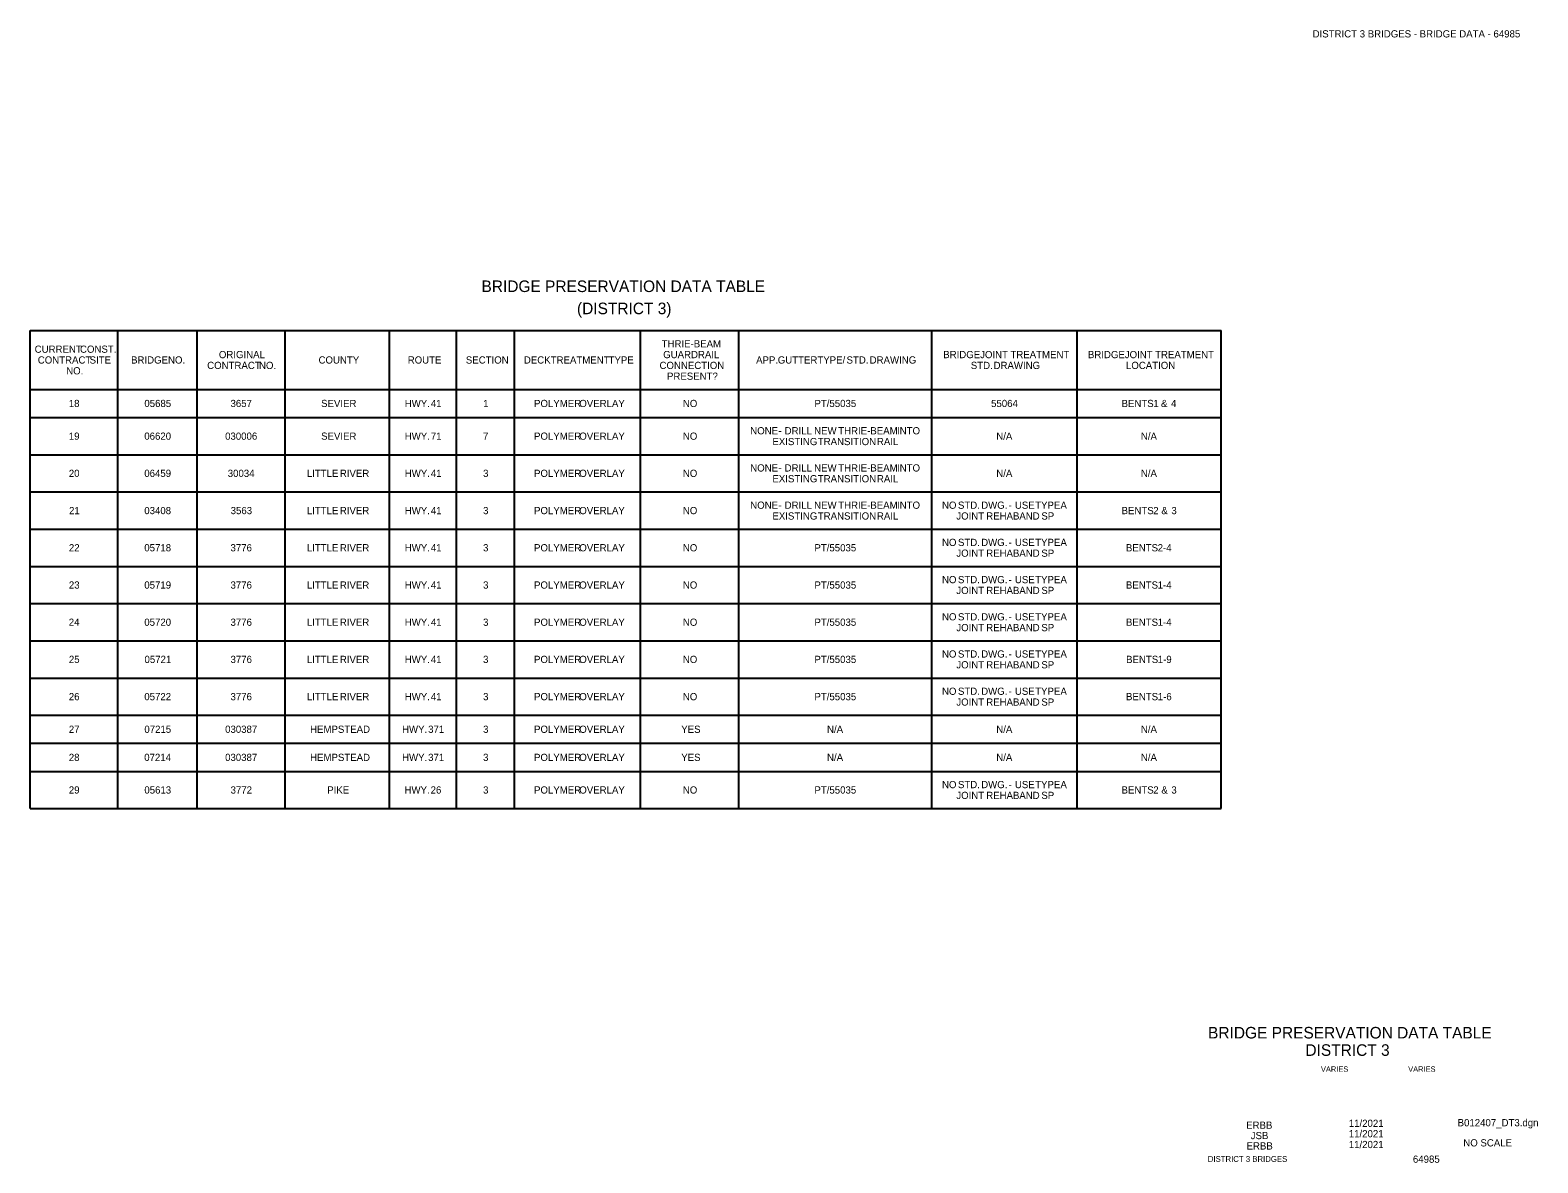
# Model space of a CAD drawing. Extents: x 16 to 1228740, y 11 to 152440.
import ezdxf

# ---------------------------------------------------------------- set-up
doc = ezdxf.new("R2010")
doc.units = 0
for name, color, linetype in [('B_border', 7, 'Continuous'), ('B_Concrete hidden', 7, 'Continuous'), ('Default', 7, 'Continuous')]:
    doc.layers.add(name, color=color, linetype=linetype)

msp = doc.modelspace()

# ---------------------------------------------------------------- linework, layer by layer
at = {"layer": 'B_border'}
msp.add_line((16.2529, 11.9714), (16.2529, 11.9714), dxfattribs=at)
at = {"layer": 'Default'}
for p, q in [((16.2529, 11.9714), (17.9726, 11.9714)), ((16.2529, 11.2809), (16.2529, 11.9714)), ((16.3796, 11.2809), (16.3796, 11.9714)), ((16.4942, 11.2809), (16.4942, 11.9714)), ((16.6209, 11.2809), (16.6209, 11.9714)), ((16.772, 11.2809), (16.772, 11.9714)), ((16.8684, 11.2809), (16.8684, 11.9714)), ((16.9525, 11.2809), (16.9525, 11.9714)), ((17.134, 11.2809), (17.134, 11.9714)), ((17.276, 11.2809), (17.276, 11.9714)), ((17.5548, 11.2809), (17.5548, 11.9714)), ((17.7647, 11.2809), (17.7647, 11.9714)), ((17.9726, 11.2809), (17.9726, 11.9714)), ((16.2529, 11.8862), (17.9726, 11.8862)), ((16.2529, 11.8457), (17.9726, 11.8457)), ((16.2529, 11.7919), (17.9726, 11.7919)), ((16.2529, 11.7382), (17.9726, 11.7382)), ((16.2529, 11.6845), (17.9726, 11.6845)), ((16.2529, 11.6307), (17.9726, 11.6307)), ((16.2529, 11.577), (17.9726, 11.577)), ((16.2529, 11.5232), (17.9726, 11.5232)), ((16.2529, 11.4695), (17.9726, 11.4695)), ((16.2529, 11.4157), (17.9726, 11.4157)), ((16.2529, 11.3752), (17.9726, 11.3752)), ((16.2529, 11.3346), (17.9726, 11.3346)), ((16.2529, 11.2809), (17.9726, 11.2809))]:
    msp.add_line(p, q, dxfattribs=at)

# ---------------------------------------------------------------- texts
at = {"layer": 'B_border'}
for s, p in [('BRIDGE PRESERVATION DATA TABLE ', (16.9046, 12.0269)), ('(DISTRICT 3)', (17.0425, 11.9949))]:
    msp.add_text(s, height=0.0167, rotation=360, dxfattribs=at).set_placement(p)
at = {"layer": 'B_Concrete hidden'}
for s, height, p in [('DISTRICT 3 BRIDGES - BRIDGE DATA - 64985', 0.0104, (18.1048, 12.3946)), ('BRIDGE PRESERVATION DATA TABLE', 0.0167, (17.9538, 10.9489)), ('DISTRICT 3', 0.0167, (18.0944, 10.9238)), ('VARIES', 0.0078, (18.1168, 10.9008)), ('VARIES', 0.0078, (18.2428, 10.9008)), ('ERBB', 0.0104, (18.0088, 10.8185)), ('11/2021', 0.0104, (18.157, 10.8212)), ('B012407_DT3.dgn', 0.0104, (18.3142, 10.8221)), ('ERBB', 0.0104, (18.0094, 10.7885)), ('JSB', 0.0104, (18.0154, 10.8035)), ('11/2021', 0.0104, (18.157, 10.8062)), ('11/2021', 0.0104, (18.157, 10.7906)), ('NO SCALE', 0.0104, (18.3224, 10.793)), ('DISTRICT 3 BRIDGES', 0.0084, (17.9534, 10.7707)), ('64985', 0.01042, (18.2496, 10.7694))]:
    msp.add_text(s, height=height, dxfattribs=at).set_placement(p)
at = {"layer": 'Default'}
for s, p in [('THRIE-BEAM', (17.1648, 11.947)), ('CURRENT', (16.2594, 11.9392)), ('CONTRACT', (16.2639, 11.9236)), (' CONST.', (16.321, 11.9392)), (' SITE', (16.3349, 11.9236)), ('BRIDGE', (16.3986, 11.9236)), (' NO.', (16.4481, 11.9236)), ('ORIGINAL', (16.5254, 11.9314)), ('COUNTY', (16.6693, 11.9236)), ('ROUTE', (16.7981, 11.9236)), ('SECTION', (16.882, 11.9236)), ('DECK', (16.9658, 11.9236)), (' TREATMENT', (17.0007, 11.9236)), (' TYPE', (17.0843, 11.9236)), ('GUARDRAIL', (17.167, 11.9314)), ('APP.', (17.3012, 11.9236)), (' GUTTER', (17.3286, 11.9236)), (' TYPE/', (17.3858, 11.9236)), (' STD.', (17.4279, 11.9236)), (' DRAWING', (17.4613, 11.9236)), ('BRIDGE', (17.5714, 11.9314)), (' JOINT', (17.6208, 11.9314)), (' TREATMENT', (17.6646, 11.9314)), ('BRIDGE', (17.7803, 11.9314)), (' JOINT', (17.8297, 11.9314)), (' TREATMENT', (17.8735, 11.9314)), ('NO.', (16.3049, 11.908)), ('CONTRACT', (16.5085, 11.9158)), (' NO.', (16.5795, 11.9158)), ('CONNECTION', (17.1617, 11.9158)), ('PRESENT?', (17.1725, 11.9002)), ('STD.', (17.6112, 11.9158)), (' DRAWING', (17.6402, 11.9158)), ('LOCATION', (17.8353, 11.9158)), ('18', (16.3087, 11.8608)), ('05685', (16.4178, 11.8608)), ('3657', (16.5422, 11.8608)), ('SEVIER', (16.673, 11.8608)), ('HWY.', (16.7938, 11.8608)), (' 41', (16.8276, 11.8608)), ('1', (16.9071, 11.8608)), ('POLYMER', (16.9805, 11.8608)), (' OVERLAY', (17.042, 11.8608)), ('NO', (17.1954, 11.8608)), ('PT/55035', (17.3854, 11.8608)), ('55064', (17.6405, 11.8608)), ('BENTS', (17.8289, 11.8608)), (' 1', (17.8709, 11.8608)), (' &', (17.882, 11.8608)), (' 4', (17.8965, 11.8608)), ('19', (16.3087, 11.8136)), ('06620', (16.4177, 11.8136)), ('030006', (16.5344, 11.8136)), ('SEVIER', (16.673, 11.8136)), ('HWY.', (16.7938, 11.8136)), (' 71', (16.8276, 11.8136)), ('7', (16.9068, 11.8136)), ('POLYMER', (16.9805, 11.8136)), (' OVERLAY', (17.042, 11.8136)), ('NO', (17.1954, 11.8136)), ('NONE', (17.2927, 11.8214)), (' -', (17.3295, 11.8214)), (' DRILL', (17.3385, 11.8214)), (' NEW', (17.3811, 11.8214)), (' THRIE-BEAM', (17.4159, 11.8214)), (' INTO', (17.5008, 11.8214)), ('N/A', (17.648, 11.8136)), ('N/A', (17.8568, 11.8136)), ('EXISTING', (17.3247, 11.8058)), (' TRANSITION', (17.3864, 11.8058)), (' RAIL', (17.4718, 11.8058)), ('20', (16.3087, 11.7599)), ('06459', (16.4177, 11.7599)), ('30034', (16.5382, 11.7599)), ('LITTLE', (16.6524, 11.7599)), (' RIVER', (16.6962, 11.7599)), ('HWY.', (16.7938, 11.7599)), (' 41', (16.8276, 11.7599)), ('3', (16.9069, 11.7599)), ('POLYMER', (16.9805, 11.7599)), (' OVERLAY', (17.042, 11.7599)), ('NO', (17.1954, 11.7599)), ('NONE', (17.2927, 11.7677)), ('EXISTING', (17.3247, 11.7521)), (' -', (17.3295, 11.7677)), (' DRILL', (17.3385, 11.7677)), (' NEW', (17.3811, 11.7677)), (' TRANSITION', (17.3864, 11.7521)), (' THRIE-BEAM', (17.4159, 11.7677)), (' RAIL', (17.4718, 11.7521)), (' INTO', (17.5008, 11.7677)), ('N/A', (17.648, 11.7599)), ('N/A', (17.8568, 11.7599)), ('21', (16.309, 11.7061)), ('03408', (16.4177, 11.7061)), ('3563', (16.5424, 11.7061)), ('LITTLE', (16.6524, 11.7061)), (' RIVER', (16.6962, 11.7061)), ('HWY.', (16.7938, 11.7061)), (' 41', (16.8276, 11.7061)), ('3', (16.9069, 11.7061)), ('POLYMER', (16.9805, 11.7061)), (' OVERLAY', (17.042, 11.7061)), ('NO', (17.1954, 11.7061)), ('NONE', (17.2927, 11.7139)), (' -', (17.3295, 11.7139)), (' DRILL', (17.3385, 11.7139)), (' NEW', (17.3811, 11.7139)), (' THRIE-BEAM', (17.4159, 11.7139)), (' INTO', (17.5008, 11.7139)), ('NO', (17.5696, 11.7139)), (' STD.', (17.5888, 11.7139)), (' DWG.', (17.6223, 11.7139)), (' -', (17.6619, 11.7139)), (' USE', (17.671, 11.7139)), (' TYPE', (17.7003, 11.7139)), (' A', (17.7368, 11.7139)), ('BENTS', (17.8289, 11.7061)), (' 2', (17.8708, 11.7061)), (' &', (17.8825, 11.7061)), (' 3', (17.897, 11.7061)), ('EXISTING', (17.3247, 11.6983)), (' TRANSITION', (17.3864, 11.6983)), (' RAIL', (17.4718, 11.6983)), ('JOINT', (17.5903, 11.6983)), (' REHAB', (17.6296, 11.6983)), (' AND', (17.6774, 11.6983)), (' SP', (17.7092, 11.6983)), ('NO', (17.5696, 11.6602)), (' STD.', (17.5888, 11.6602)), (' DWG.', (17.6223, 11.6602)), (' USE', (17.671, 11.6602)), (' TYPE', (17.7003, 11.6602)), (' A', (17.7368, 11.6602)), ('22', (16.3088, 11.6524)), ('05718', (16.4177, 11.6524)), ('3776', (16.5422, 11.6524)), ('LITTLE', (16.6524, 11.6524)), (' RIVER', (16.6962, 11.6524)), ('HWY.', (16.7938, 11.6524)), (' 41', (16.8276, 11.6524)), ('3', (16.9069, 11.6524)), ('POLYMER', (16.9805, 11.6524)), (' OVERLAY', (17.042, 11.6524)), ('NO', (17.1954, 11.6524)), ('PT/55035', (17.3854, 11.6524)), ('JOINT', (17.5903, 11.6446)), (' REHAB', (17.6296, 11.6446)), (' -', (17.6619, 11.6602)), (' AND', (17.6774, 11.6446)), (' SP', (17.7092, 11.6446)), ('BENTS', (17.8352, 11.6524)), (' 2-4', (17.8772, 11.6524)), ('23', (16.3088, 11.5986)), ('05719', (16.4177, 11.5986)), ('3776', (16.5422, 11.5986)), ('LITTLE', (16.6524, 11.5986)), (' RIVER', (16.6962, 11.5986)), ('HWY.', (16.7938, 11.5986)), (' 41', (16.8276, 11.5986)), ('3', (16.9069, 11.5986)), ('POLYMER', (16.9805, 11.5986)), (' OVERLAY', (17.042, 11.5986)), ('NO', (17.1954, 11.5986)), ('PT/55035', (17.3854, 11.5986)), ('NO', (17.5696, 11.6064)), (' STD.', (17.5888, 11.6064)), (' DWG.', (17.6223, 11.6064)), (' -', (17.6619, 11.6064)), (' USE', (17.671, 11.6064)), (' TYPE', (17.7003, 11.6064)), (' A', (17.7368, 11.6064)), ('BENTS', (17.8352, 11.5986)), (' 1-4', (17.8772, 11.5986)), ('JOINT', (17.5903, 11.5908)), (' REHAB', (17.6296, 11.5908)), (' AND', (17.6774, 11.5908)), (' SP', (17.7092, 11.5908)), ('NO', (17.5696, 11.5527)), (' STD.', (17.5888, 11.5527)), (' DWG.', (17.6223, 11.5527)), (' USE', (17.671, 11.5527)), (' TYPE', (17.7003, 11.5527)), (' A', (17.7368, 11.5527)), ('24', (16.3086, 11.5449)), ('05720', (16.4177, 11.5449)), ('3776', (16.5422, 11.5449)), ('LITTLE', (16.6524, 11.5449)), (' RIVER', (16.6962, 11.5449)), ('HWY.', (16.7938, 11.5449)), (' 41', (16.8276, 11.5449)), ('3', (16.9069, 11.5449)), ('POLYMER', (16.9805, 11.5449)), (' OVERLAY', (17.042, 11.5449)), ('NO', (17.1954, 11.5449)), ('PT/55035', (17.3854, 11.5449)), ('JOINT', (17.5903, 11.5371)), (' REHAB', (17.6296, 11.5371)), (' -', (17.6619, 11.5527)), (' AND', (17.6774, 11.5371)), (' SP', (17.7092, 11.5371)), ('BENTS', (17.8352, 11.5449)), (' 1-4', (17.8772, 11.5449)), ('25', (16.3088, 11.4912)), ('05721', (16.418, 11.4912)), ('3776', (16.5422, 11.4912)), ('LITTLE', (16.6524, 11.4912)), (' RIVER', (16.6962, 11.4912)), ('HWY.', (16.7938, 11.4912)), (' 41', (16.8276, 11.4912)), ('3', (16.9069, 11.4912)), ('POLYMER', (16.9805, 11.4912)), (' OVERLAY', (17.042, 11.4912)), ('NO', (17.1954, 11.4912)), ('PT/55035', (17.3854, 11.4912)), ('NO', (17.5696, 11.499)), (' STD.', (17.5888, 11.499)), (' DWG.', (17.6223, 11.499)), (' -', (17.6619, 11.499)), (' USE', (17.671, 11.499)), (' TYPE', (17.7003, 11.499)), (' A', (17.7368, 11.499)), ('BENTS', (17.8354, 11.4912)), (' 1-9', (17.8773, 11.4912)), ('JOINT', (17.5903, 11.4834)), (' REHAB', (17.6296, 11.4834)), (' AND', (17.6774, 11.4834)), (' SP', (17.7092, 11.4834)), ('NO', (17.5696, 11.4452)), (' STD.', (17.5888, 11.4452)), (' DWG.', (17.6223, 11.4452)), (' USE', (17.671, 11.4452)), (' TYPE', (17.7003, 11.4452)), (' A', (17.7368, 11.4452)), ('26', (16.3087, 11.4374)), ('05722', (16.4177, 11.4374)), ('3776', (16.5422, 11.4374)), ('LITTLE', (16.6524, 11.4374)), (' RIVER', (16.6962, 11.4374)), ('HWY.', (16.7938, 11.4374)), (' 41', (16.8276, 11.4374)), ('3', (16.9069, 11.4374)), ('POLYMER', (16.9805, 11.4374)), (' OVERLAY', (17.042, 11.4374)), ('NO', (17.1954, 11.4374)), ('PT/55035', (17.3854, 11.4374)), ('JOINT', (17.5903, 11.4296)), (' REHAB', (17.6296, 11.4296)), (' -', (17.6619, 11.4452)), (' AND', (17.6774, 11.4296)), (' SP', (17.7092, 11.4296)), ('BENTS', (17.8353, 11.4374)), (' 1-6', (17.8773, 11.4374)), ('27', (16.3087, 11.3903)), ('07215', (16.4178, 11.3903)), ('030387', (16.5344, 11.3903)), ('HEMPSTEAD', (16.6571, 11.3903)), ('HWY.', (16.7899, 11.3903)), (' 371', (16.8237, 11.3903)), ('3', (16.9069, 11.3903)), ('POLYMER', (16.9805, 11.3903)), (' OVERLAY', (17.042, 11.3903)), ('YES', (17.1931, 11.3903)), ('N/A', (17.4036, 11.3903)), ('N/A', (17.648, 11.3903)), ('N/A', (17.8568, 11.3903)), ('28', (16.3087, 11.3497)), ('07214', (16.4176, 11.3497)), ('030387', (16.5344, 11.3497)), ('HEMPSTEAD', (16.6571, 11.3497)), ('HWY.', (16.7899, 11.3497)), (' 371', (16.8237, 11.3497)), ('3', (16.9069, 11.3497)), ('POLYMER', (16.9805, 11.3497)), (' OVERLAY', (17.042, 11.3497)), ('YES', (17.1931, 11.3497)), ('N/A', (17.4036, 11.3497)), ('N/A', (17.648, 11.3497)), ('N/A', (17.8568, 11.3497)), ('29', (16.3087, 11.3026)), ('05613', (16.4178, 11.3026)), ('3772', (16.5423, 11.3026)), ('PIKE', (16.6819, 11.3026)), ('HWY.', (16.7935, 11.3026)), (' 26', (16.8273, 11.3026)), ('3', (16.9069, 11.3026)), ('POLYMER', (16.9805, 11.3026)), (' OVERLAY', (17.042, 11.3026)), ('NO', (17.1954, 11.3026)), ('PT/55035', (17.3854, 11.3026)), ('NO', (17.5696, 11.3104)), ('JOINT', (17.5903, 11.2948)), (' STD.', (17.5888, 11.3104)), (' DWG.', (17.6223, 11.3104)), (' REHAB', (17.6296, 11.2948)), (' -', (17.6619, 11.3104)), (' USE', (17.671, 11.3104)), (' AND', (17.6774, 11.2948)), (' TYPE', (17.7003, 11.3104)), (' SP', (17.7092, 11.2948)), (' A', (17.7368, 11.3104)), ('BENTS', (17.8289, 11.3026)), (' 2', (17.8708, 11.3026)), (' &', (17.8825, 11.3026)), (' 3', (17.897, 11.3026))]:
    msp.add_text(s, height=0.0104, dxfattribs=at).set_placement(p)

doc.saveas('drawing.dxf')
